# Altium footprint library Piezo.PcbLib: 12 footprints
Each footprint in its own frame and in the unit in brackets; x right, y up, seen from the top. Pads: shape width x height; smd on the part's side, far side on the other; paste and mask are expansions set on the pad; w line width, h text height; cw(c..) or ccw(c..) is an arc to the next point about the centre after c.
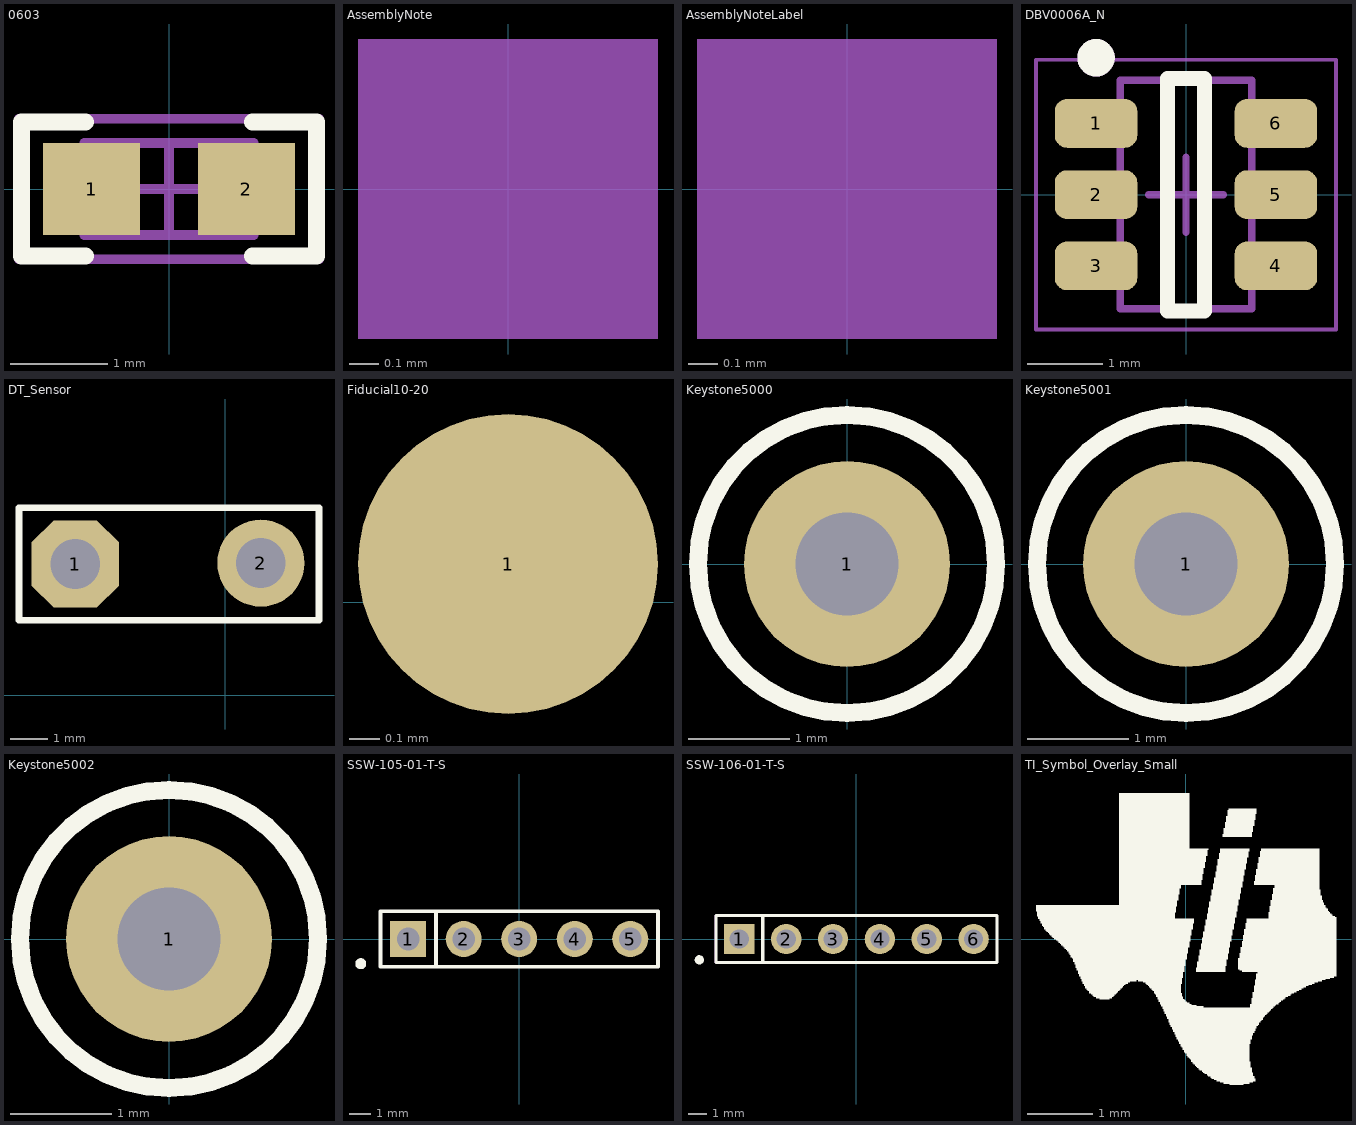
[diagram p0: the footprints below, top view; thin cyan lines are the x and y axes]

## 0603 [mm] "0603 from SM-752 data"
height 0.85
pads (2):
  rect 1x0.95 smd: 1(-0.8,0) 2(0.8,0)
Top Overlay:
  lines w0.178: -0.864,-0.691 -1.524,-0.691 -1.524,0.693 -0.864,0.693 ; 0.864,-0.691 1.524,-0.691 1.524,0.693 0.864,0.693
Mechanical 5:
  lines w0.1: -1.55,-0.725 -1.55,0.725 1.55,0.725 1.55,-0.725 -1.55,-0.725
  text ".Designator" at -0.279,0.076 h0.76
Mechanical 13:
  lines w0.1: -0.55,-0.475 -0.55,0.475 ; 0.55,-0.475 0.55,0.475 ; -0.875,-0.475 0.875,-0.475 0.875,0.475 -0.875,0.475 -0.875,-0.475
Mechanical 15:
  lines w0.1: -0.475,0 0.475,0 ; 0,-0.475 0,0.475 ; -1.55,-0.725 1.55,-0.725 1.55,0.725 -1.55,0.725 -1.55,-0.725
3D body: height 0.85, standoff 0, extent -0.874,-0.474 -0.551,0.474
3D body: height 0.85, standoff 0, extent -0.549,-0.474 0.549,0.474
3D body: height 0.85, standoff 0, extent 0.551,-0.474 0.874,0.474

## AssemblyNote [mm] "Assembly Note"
Mechanical 5:
  rectangle: -0.508,-0.508 0.508,0.508
  text ".Designator" at -4.191,-0.508 h1.02
  text ".Comment" at 1.143,-0.508 h1.02

## AssemblyNoteLabel [mm] "Assembly Note for PCB Labels"
Mechanical 5:
  rectangle: -0.508,-0.508 0.508,0.508
  text "Install label in silkscreened box after final wash.  Text shall be 8 pt font. Text shall be per Table 1" at 1.143,-0.508 h1.02
  text ".Designator" at -4.191,-0.508 h1.02

## DBV0006A_N [mm] "SOT23, 6-Leads, Body 2.9x1.6mm, Pitch 0.95mm, Lead Span 2.8mm, IPC Medium Density"
height 1.45
pads (6):
  rrect50% 1.1x0.65 smd: 1(-1.2,0.95) 2(-1.2,0) 3(-1.2,-0.95) 4(1.2,-0.95) 5(1.2,0) 6(1.2,0.95)
Top Overlay:
  circle w0.25: c-1.2,1.825 r0.125
  lines w0.2: -0.25,-1.55 -0.25,1.55 0.25,1.55 0.25,-1.55 -0.25,-1.55
Mechanical 5:
  circle w0.25: c-1.2,1.825 r0.125
  lines w0.1: -0.875,-1.525 0.875,-1.525 0.875,1.525 -0.875,1.525 -0.875,-1.525
  text ".Designator" at -0.254,1.27 h0.51
Mechanical 15:
  lines w0.05: -2,-1.8 2,-1.8 2,1.8 -2,1.8 -2,-1.8
  lines w0.1: -0.5,0 0.5,0 ; 0,-0.5 0,0.5
3D body: height 1.45, standoff 0, extent -0.875,-1.525 0.875,1.525

## DT_Sensor [mil]
pads (2):
  oct 93x93 hole 53: 1(-160,140)
  round 93 hole 53: 2(38,141)
Top Overlay:
  lines w7: -220,80 100,80 100,200 -220,200 -220,80

## Fiducial10-20 [mm]
pads (1):
  round 1 smd paste-0.5 mask+0.5: 1(-1.778,0.127)

## Keystone5000 [mil] "For Keystone 500x miniature loop terminals"
height 181.1
pads (1):
  round 80 hole 40: 1(0,0)
Top Overlay:
  circle w7: c0,0 r58
Mechanical 5:
  circle w5: c0,0 r58.31
  text ".Designator" at -48,-14 h30
3D body: height 181.97, standoff -118.11, extent -49,-49 49.04,49.24

## Keystone5001 [mil] "For Keystone 500x miniature loop terminals"
height 181.1
pads (1):
  round 80 hole 40: 1(0,0)
Top Overlay:
  circle w7: c0,0 r58
Mechanical 5:
  circle w5: c0,0 r58.31
  text ".Designator" at -45,-10 h30
3D body: height 181.97, standoff -118.11, extent -49,-49 49.04,49.24

## Keystone5002 [mil] "For Keystone 500x miniature loop terminals"
height 181.1
pads (1):
  round 80 hole 40: 1(0,0)
Top Overlay:
  circle w7: c0,0 r58
Mechanical 5:
  circle w5: c0,0 r58.31
  text ".Designator" at -45,-10 h30
3D body: height 181.97, standoff -118.11, extent -49,-49 49.04,49.23

## SSW-105-01-T-S [mm] "Samtec 100mil, 1x5, 230 mil above insulator"
height 8.382
pads (5):
  rect 1.65x1.65 hole 1.041 mask+0: 1(-5.08,0)
  round 1.65 hole 1.041 mask+0: 2(-2.54,0) 3(0,0) 4(2.54,0) 5(5.08,0)
Top Overlay:
  circle w0.25: c-7.25,-1.13 r0.125
  lines w0.178: -3.81,-1.27 -3.81,1.27 ; -6.35,-1.27 -6.35,1.27 6.35,1.27 6.35,-1.27 -6.35,-1.27
Mechanical 5:
  rectangle: -5.588,-0.508 -4.572,0.508
  lines w0.127: -6.35,-1.27 6.35,-1.27 6.35,1.27 -6.35,1.27 -6.35,-1.27
  text ".Designator" at -1.524,-0.508 h1.02
3D body: height 8.38, standoff -2.54, extent -6.35,-1.27 6.35,1.27

## SSW-106-01-T-S [mm] "Samtec 100mil, 1x6, 230 mil above insulator"
height 8.382
pads (6):
  rect 1.65x1.65 hole 1.041 mask+0: 1(-6.35,0)
  round 1.65 hole 1.041 mask+0: 2(-3.81,0) 3(-1.27,0) 4(1.27,0) 5(3.81,0) 6(6.35,0)
Top Overlay:
  circle w0.25: c-8.52,-1.13 r0.125
  lines w0.178: -5.08,-1.27 -5.08,1.27 ; -7.62,-1.27 -7.62,1.27 7.62,1.27 7.62,-1.27 -7.62,-1.27
Mechanical 5:
  rectangle: -6.858,-0.508 -5.842,0.508
  lines w0.127: -7.62,-1.27 7.62,-1.27 7.62,1.27 -7.62,1.27 -7.62,-1.27
  text ".Designator" at -1.524,-0.508 h1.02
3D body: height 8.38, standoff -2.54, extent -7.62,-1.27 7.62,1.27

## TI_Symbol_Overlay_Small [mm]
Top Overlay:
  drawing of 3 lines, arcs and shapes, not listed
